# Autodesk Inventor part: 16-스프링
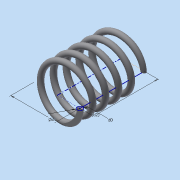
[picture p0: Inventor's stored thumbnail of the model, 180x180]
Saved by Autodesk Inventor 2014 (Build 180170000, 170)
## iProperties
Created: 2016-01
Part Number: 16-스프링
Material: 강철, 탄소
Document SubType Name: Modeling
Designer: Administrator
Density: 7.87 g/cm^3
Appearance: 반연마
Mass: 6.44239 g
Surface Area: 16.6857 cm^2
Volume: 0.818602 cm^3
Author: Administrator
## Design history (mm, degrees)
sketch "스케치1"
  geometry: L1 (0, 0)-(0, 17.5); L2 (0, 17.5)-(8.5, 17.5); L3 (8.5, 17.5)-(8.5, 0); L4 (8.5, 0)-(0, 0); C1 r 1 at (8.5, 0)
  constraints: 8 end point, 2 parallel, 1 centre point, 1 coincident, 1 perpendicular, 1 vertical
  dimensions: "d0" = 2 diameter of C1; "d1" = 17 diameter of L3 L1; "d2" = 17.5 distance between parallel lines of L4 L2 (derived)
feature "코일1" pitch "d3" = 10; turns "d5" = 5; dims "d4" = 17.5 (= d2), "d6" = 0, angle "d7" = 90 deg, angle "d8" = 90 deg, "d9" = 0, "d10" = 0
node "작업 평면1"
sketch "스케치2"
  geometry: L1 (-9.5, 0)-(-7.5, 0) reference; L2 (-9.5, 0)-(-7.5, 0) reference; 1 further point
  constraints: 2 horizontal alignment
extrude "돌출1" cut sketch "스케치2" distance "d12" = 10; taper "d13" = 0 deg
node "작업 평면2"
sketch "스케치3"
  geometry: L1 (-7.5, 0)-(-9.5, 0) reference; 1 further point
  constraints: 1 horizontal alignment
extrude "돌출2" cut sketch "스케치3" distance "d15" = 10; taper "d16" = 0 deg
node "솔리드1"
node "절단 모서리 투영1"
node "절단 모서리 투영2"
node "절단 모서리 투영3"
other parameters: "d11" = 0, "d14" = 17.5 (= d2)
